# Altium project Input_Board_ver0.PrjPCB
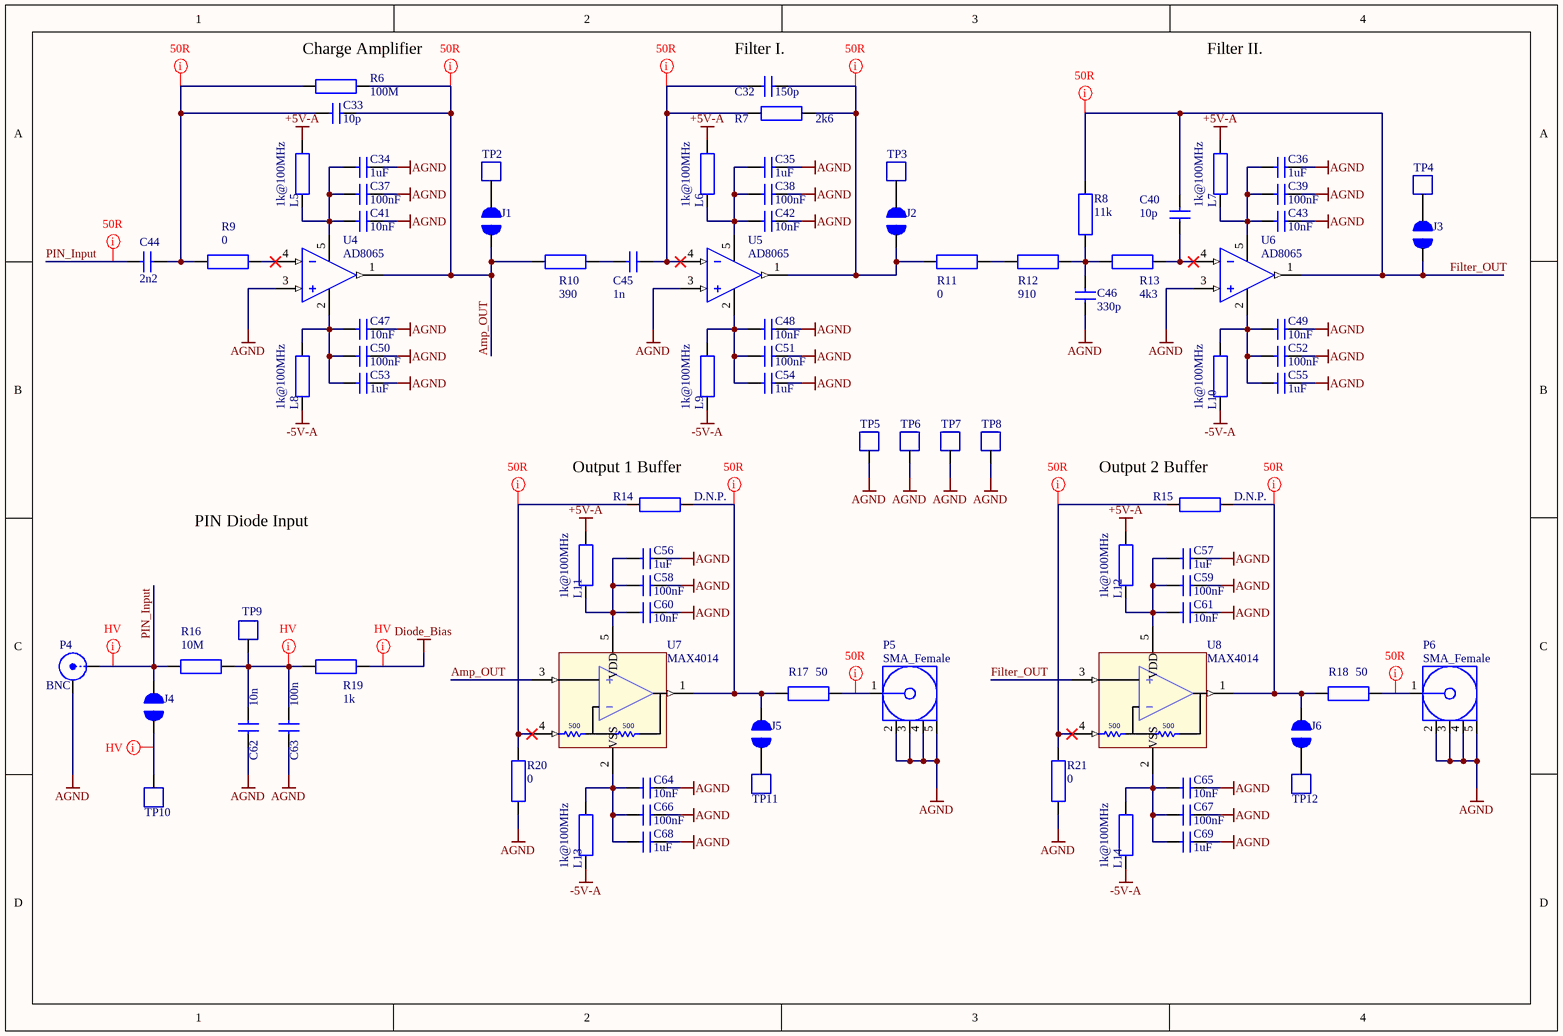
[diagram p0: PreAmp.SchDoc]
2 sheets, 143 parts. Net scope: global (net labels, ports and power ports of the same name join across sheets).
Board file: Input_Board_ver0.PcbDoc
Sheets:
  PreAmp.SchDoc
  Power.SchDoc

## Sheet PreAmp.SchDoc: Input Board - Pre Amp
size A4; Author: Tomáš Kulhánek; Revision: 0; SheetNumber: 1; SheetTotal: 2

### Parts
C32  150p  [SMD_CAPACITOR_0603]
C33  10p  [SMD_CAPACITOR_0603]
C34  1uF  [SMD_CAPACITOR_0603]
C35  1uF  [SMD_CAPACITOR_0603]
C36  1uF  [SMD_CAPACITOR_0603]
C37  100nF  [SMD_CAPACITOR_0603]
C38  100nF  [SMD_CAPACITOR_0603]
C39  100nF  [SMD_CAPACITOR_0603]
C40  10p  [SMD_CAPACITOR_0603]
C41  10nF  [SMD_CAPACITOR_0603]
C42  10nF  [SMD_CAPACITOR_0603]
C43  10nF  [SMD_CAPACITOR_0603]
C44  2n2  [SMD_CAPACITOR_1206]
C45  1n  [SMD_CAPACITOR_0603]
C46  330p  [SMD_CAPACITOR_0603]
C47  10nF  [SMD_CAPACITOR_0603]
C48  10nF  [SMD_CAPACITOR_0603]
C49  10nF  [SMD_CAPACITOR_0603]
C50  100nF  [SMD_CAPACITOR_0603]
C51  100nF  [SMD_CAPACITOR_0603]
C52  100nF  [SMD_CAPACITOR_0603]
C53  1uF  [SMD_CAPACITOR_0603]
C54  1uF  [SMD_CAPACITOR_0603]
C55  1uF  [SMD_CAPACITOR_0603]
C56  1uF  [SMD_CAPACITOR_0603]
C57  1uF  [SMD_CAPACITOR_0603]
C58  100nF  [SMD_CAPACITOR_0603]
C59  100nF  [SMD_CAPACITOR_0603]
C60  10nF  [SMD_CAPACITOR_0603]
C61  10nF  [SMD_CAPACITOR_0603]
C62  10n  [SMD_CAPACITOR_1206]
C63  100n  [SMD_CAPACITOR_1206]
C64  10nF  [SMD_CAPACITOR_0603]
C65  10nF  [SMD_CAPACITOR_0603]
C66  100nF  [SMD_CAPACITOR_0603]
C67  100nF  [SMD_CAPACITOR_0603]
C68  1uF  [SMD_CAPACITOR_0603]
C69  1uF  [SMD_CAPACITOR_0603]
J1  SB  [SOLDER_BRIDGE_1MM]  (value not drawn)
J2  SB  [SOLDER_BRIDGE_1MM]  (value not drawn)
J3  SB  [SOLDER_BRIDGE_1MM]  (value not drawn)
J4  SB  [SOLDER_BRIDGE_1MM]  (value not drawn)
J5  SB  [SOLDER_BRIDGE_1MM]  (value not drawn)
J6  SB  [SOLDER_BRIDGE_1MM]  (value not drawn)
L5  1k@100MHz  [SMD_RES_0603]
L6  1k@100MHz  [SMD_RES_0603]
L7  1k@100MHz  [SMD_RES_0603]
L8  1k@100MHz  [SMD_RES_0603]
L9  1k@100MHz  [SMD_RES_0603]
L10  1k@100MHz  [SMD_RES_0603]
L11  1k@100MHz  [SMD_RES_0603]
L12  1k@100MHz  [SMD_RES_0603]
L13  1k@100MHz  [SMD_RES_0603]
L14  1k@100MHz  [SMD_RES_0603]
P4  BNC  [BNC_0315637]
P5  SMA_Female  [SMA5.08-H]
P6  SMA_Female  [SMA5.08-H]
R6  100M  [SMD_RES_0603]
R7  2k6  [SMD_RES_0603]
R8  11k  [SMD_RES_0603]
R9  0  [SMD_RES_0603]
R10  390  [SMD_RES_0603]
R11  0  [SMD_RES_0603]
R12  910  [SMD_RES_0603]
R13  4k3  [SMD_RES_0603]
R14  D.N.P.  [SMD_RES_0603]
R15  D.N.P.  [SMD_RES_0603]
R16  10M  [SMD_RESISTOR_1206]
R17  50  [SMD_RES_0603]
R18  50  [SMD_RES_0603]
R19  1k  [SMD_RESISTOR_1206]
R20  0  [SMD_RES_0603]
R21  0  [SMD_RES_0603]
TP2  Test Pin  [PIn_1mm]  (value not drawn)
TP3  Test Pin  [PIn_1mm]  (value not drawn)
TP4  Test Pin  [PIn_1mm]  (value not drawn)
TP5  Test Pin  [PIn_1mm]  (value not drawn)
TP6  Test Pin  [PIn_1mm]  (value not drawn)
TP7  Test Pin  [PIn_1mm]  (value not drawn)
TP8  Test Pin  [PIn_1mm]  (value not drawn)
TP9  Test Pin  [PIn_1mm]  (value not drawn)
TP10  Test Pin  [PIn_1mm]  (value not drawn)
TP11  Test Pin  [PIn_1mm]  (value not drawn)
TP12  Test Pin  [PIn_1mm]  (value not drawn)
U4  AD8065  [SMD_SOT-23-5]
U5  AD8065  [SMD_SOT-23-5]
U6  AD8065  [SMD_SOT-23-5]
U7  MAX4014  [SMD_SOT-23-5]
U8  MAX4014  [SMD_SOT-23-5]

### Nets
+5V-A: L5.2 L6.2 L7.2 L11.2 L12.2
-5V-A: L8.1 L9.1 L10.1 L13.1 L14.1
AGND: C34.2 C35.2 C36.2 C37.2 C38.2 C39.2 C41.2 C42.2 C43.2 C46.1 C47.2 C48.2 C49.2 C50.2 C51.2 C52.2 C53.2 C54.2 C55.2 C56.2 C57.2 C58.2 C59.2 C60.2 C61.2 C62.1 C63.1 C64.2 C65.2 C66.2 C67.2 C68.2 C69.2 P4.1(Y) P5.2(GND) P5.3(GND) P5.4(GND) P5.5(GND) P6.2(GND) P6.3(GND) P6.4(GND) P6.5(GND) R20.1 R21.1 TP5.1 TP6.1 TP7.1 TP8.1 U4.3 U5.3 U6.3
Diode_Bias: R19.2
Amp_OUT: C33.2 J1.1 R6.2 R10.1 U4.1 U7.3
Filter_OUT: C40.2 J3.1 R8.2 U6.1 U8.3
PIN_Input: C44.1 J4.2 P4.2(X) R16.1
NetC32_1: C32.1 C45.2 R7.1 U5.4
NetC32_2: C32.2 J2.1 R7.2 R11.1 U5.1
NetC33_1: C33.1 C44.2 R6.1 R9.1
NetC34_1: C34.1 C37.1 C41.1 L5.1 U4.5(VDD)
NetC35_1: C35.1 C38.1 C42.1 L6.1 U5.5(VDD)
NetC36_1: C36.1 C39.1 C43.1 L7.1 U6.5(VDD)
NetC40_1: C40.1 R13.2 U6.4
NetC45_1: C45.1 R10.2
NetC46_2: C46.2 R8.1 R12.2 R13.1
NetC47_1: C47.1 C50.1 C53.1 L8.2 U4.2(VSS)
NetC48_1: C48.1 C51.1 C54.1 L9.2 U5.2(VSS)
NetC49_1: C49.1 C52.1 C55.1 L10.2 U6.2(VSS)
NetC56_1: C56.1 C58.1 C60.1 L11.1 U7.5(VDD)
NetC57_1: C57.1 C59.1 C61.1 L12.1 U8.5(VDD)
NetC62_2: C62.2 C63.2 R16.2 R19.1 TP9.1
NetC64_1: C64.1 C66.1 C68.1 L13.2 U7.2(VSS)
NetC65_1: C65.1 C67.1 C69.1 L14.2 U8.2(VSS)
NetJ1_2: J1.2 TP2.1
NetJ2_2: J2.2 TP3.1
NetJ3_2: J3.2 TP4.1
NetJ4_1: J4.1 TP10.1
NetJ5_1: J5.1 TP11.1
NetJ5_2: J5.2 R14.2 R17.1 U7.1
NetJ6_1: J6.1 TP12.1
NetJ6_2: J6.2 R15.2 R18.1 U8.1
NetP5_1: P5.1(Signal) R17.2
NetP6_1: P6.1(Signal) R18.2
NetR9_2: R9.2 U4.4
NetR11_2: R11.2 R12.1
NetR14_1: R14.1 R20.2 U7.4
NetR15_1: R15.1 R21.2 U8.4

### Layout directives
net class HV: Diode_Bias, NetC62_2, NetJ4_1, PIN_Input
net class 50R: Amp_OUT, Filter_OUT, NetC32_1, NetC32_2, NetC33_1, NetJ5_2, NetJ6_2, NetP5_1, NetP6_1, NetR14_1, NetR15_1, PIN_Input

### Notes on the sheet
- (near R6) Charge Amplifier
- (near C32) Filter I.
- Filter II.
- (near R14) Output 1 Buffer
- (near R15) Output 2 Buffer
- PIN Diode Input

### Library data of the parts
C32-C69 = Capacitor
J1-J6 = Solder_Bridge_1mm
L5-L14 = EMI_Ferrite_bead
R6-R21 = Resistor
TP2-TP12 = Test Pin: Connector; Manufacturer_Name: Oxley; Manufacturer_Part_Number: 050/LT/B2

## Sheet Power.SchDoc
size A4; SheetTotal: 2
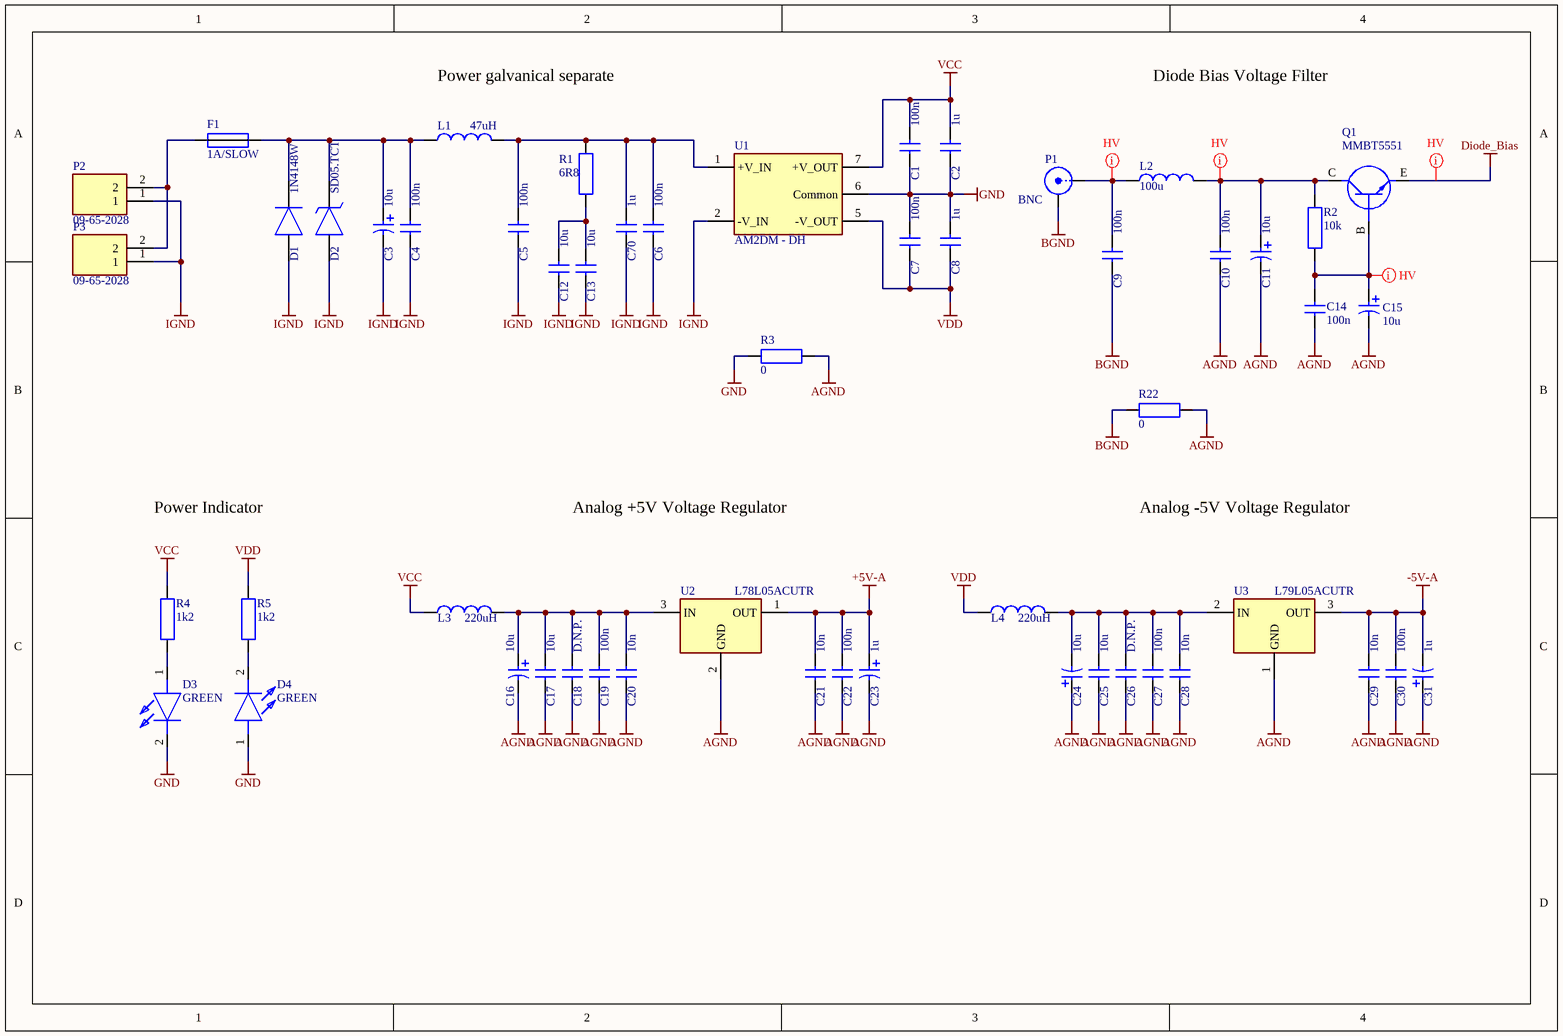
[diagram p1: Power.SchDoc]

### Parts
C1  100n  [SMD_CAPACITOR_0603]
C2  1u  [SMD_CAPACITOR_0603]
C3  10u  [SMD_CAP_POL_D5.0mm]
C4  100n  [SMD_CAPACITOR_0603]
C5  100n  [SMD_CAPACITOR_0603]
C6  100n  [SMD_CAPACITOR_0603]
C7  100n  [SMD_CAPACITOR_0603]
C8  1u  [SMD_CAPACITOR_0603]
C9  100n  [SMD_CAPACITOR_1206]
C10  100n  [SMD_CAPACITOR_1206]
C11  10u  [CAPPR5-10x25]
C12  10u  [SMD_CAPACITOR_1206]
C13  10u  [SMD_CAPACITOR_1206]
C14  100n  [SMD_CAPACITOR_1206]
C15  10u  [CAPPR5-10x25]
C16  10u  [SMD_CAP_POL_D5.0mm]
C17  10u  [SMD_CAPACITOR_1206]
C18  D.N.P.  [SMD_CAPACITOR_1206]
C19  100n  [SMD_CAPACITOR_0603]
C20  10n  [SMD_CAPACITOR_0603]
C21  10n  [SMD_CAPACITOR_0603]
C22  100n  [SMD_CAPACITOR_0603]
C23  1u  [SMD_CAPACITOR_POL_A_3216]
C24  10u  [SMD_CAP_POL_D5.0mm]
C25  10u  [SMD_CAPACITOR_1206]
C26  D.N.P.  [SMD_CAPACITOR_1206]
C27  100n  [SMD_CAPACITOR_0603]
C28  10n  [SMD_CAPACITOR_0603]
C29  10n  [SMD_CAPACITOR_0603]
C30  100n  [SMD_CAPACITOR_0603]
C31  1u  [SMD_CAPACITOR_POL_A_3216]
C70  1u  [SMD_CAPACITOR_0603]
D1  1N4148W  [SMD_SOD-123]
D2  SD05.TCT  [SMD_SOD-323]
D3  GREEN  [SMD_LED_0603]
D4  GREEN  [SMD_LED_0603]
F1  1A/SLOW  [SMD_RESISTOR_1206]
L1  47uH  [SMD_INDUCTOR_7.3MM]
L2  100u  [SMD_INDUCTOR_7.3MM]
L3  220uH  [SMD_INDUCTOR_7.3MM]
L4  220uH  [SMD_INDUCTOR_7.3MM]
P1  BNC  [BNC_0315637]
P2  09-65-2028  [SHDR2W165P0X396_1X2_716X1062X1425P]
P3  09-65-2028  [SHDR2W165P0X396_1X2_716X1062X1425P]
Q1  MMBT5551  [SMD_SOT-23]
R1  6R8  [SMD_RESISTOR_1206]
R2  10k  [SMD_RESISTOR_1206]
R3  0  [SMD_RESISTOR_0805]
R4  1k2  [SMD_RES_0603]
R5  1k2  [SMD_RES_0603]
R22  0  [SMD_RESISTOR_0805]
U1  AM2DM - DH  [AM2DM_dual_3]
U2  L78L05ACUTR  [SOT-89_N]
U3  L79L05ACUTR  [SOT-89_N]

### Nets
+5V-A: C21.2 C22.2 C23.1 U2.1(OUT)
-5V-A: C29.2 C30.2 C31.2 U3.3(OUT)
AGND: C10.1 C11.2 C14.1 C15.2 C16.2 C17.1 C18.1 C19.1 C20.1 C21.1 C22.1 C23.2 C24.1 C25.1 C26.1 C27.1 C28.1 C29.1 C30.1 C31.1 R3.2 R22.2 U2.2(GND) U3.1(GND)
BGND: C9.1 P1.1(Y) R22.1
Diode_Bias: Q1.E
GND: C1.1 C2.1 C7.2 C8.2 D3.2(K) D4.1(A) R3.1 U1.6(Common)
IGND: C3.2 C4.1 C5.1 C6.1 C12.1 C13.1 C70.1 D1.1(A) D2.1(A) P2.1 P3.1 U1.2(-V_IN)
VCC: C1.2 C2.2 L3.1 R4.1 U1.7(+V_OUT)
VDD: C7.1 C8.1 L4.1 R5.1 U1.5(-V_OUT)
NetC3_1: C3.1 C4.2 D1.2(K) D2.2(K) F1.2 L1.1
NetC5_2: C5.2 C6.2 C70.2 L1.2 R1.2 U1.1(+V_IN)
NetC9_2: C9.2 L2.1 P1.2(X)
NetC10_2: C10.2 C11.1 L2.2 Q1.C R2.2
NetC12_2: C12.2 C13.2 R1.1
NetC14_2: C14.2 C15.1 Q1.B R2.1
NetC16_1: C16.1 C17.2 C18.2 C19.2 C20.2 L3.2 U2.3(IN)
NetC24_2: C24.2 C25.2 C26.2 C27.2 C28.2 L4.2 U3.2(IN)
NetD3_1: D3.1(A) R4.2
NetD4_2: D4.2(K) R5.2
NetF1_1: F1.1 P2.2 P3.2

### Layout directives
net class HV: Diode_Bias, NetC9_2, NetC10_2, NetC14_2

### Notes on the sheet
- Power galvanical separate
- Diode Bias Voltage Filter
- Power Indicator
- Analog +5V Voltage Regulator
- Analog -5V Voltage Regulator

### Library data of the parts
C1 C2 C4-C10 C12-C14 C17-C22 C25-C30 C70 = Capacitor
C3 C11 C15 C16 C23 C24 C31 = Capacitor_pol
D1 = Diode
D2 = TVS_Diode_unidirect
D3 D4 = LED
F1 = Fuse
L1-L4 = Inductor
P2 P3 = 09-65-2028: Connector; Manufacturer_Name: Molex; Allied_Number: 70374002
Q1 = Transistor_NPN: pin to pad: B>1 C>3 E>2
R1-R5 R22 = Resistor

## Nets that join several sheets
+5V-A: PreAmp (5 pins), Power (C21.2 C22.2 C23.1 U2.1)
-5V-A: PreAmp (5 pins), Power (C29.2 C30.2 C31.2 U3.3)
AGND: PreAmp (51 pins), Power (24 pins)
Diode_Bias: PreAmp (R19.2), Power (Q1.E)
